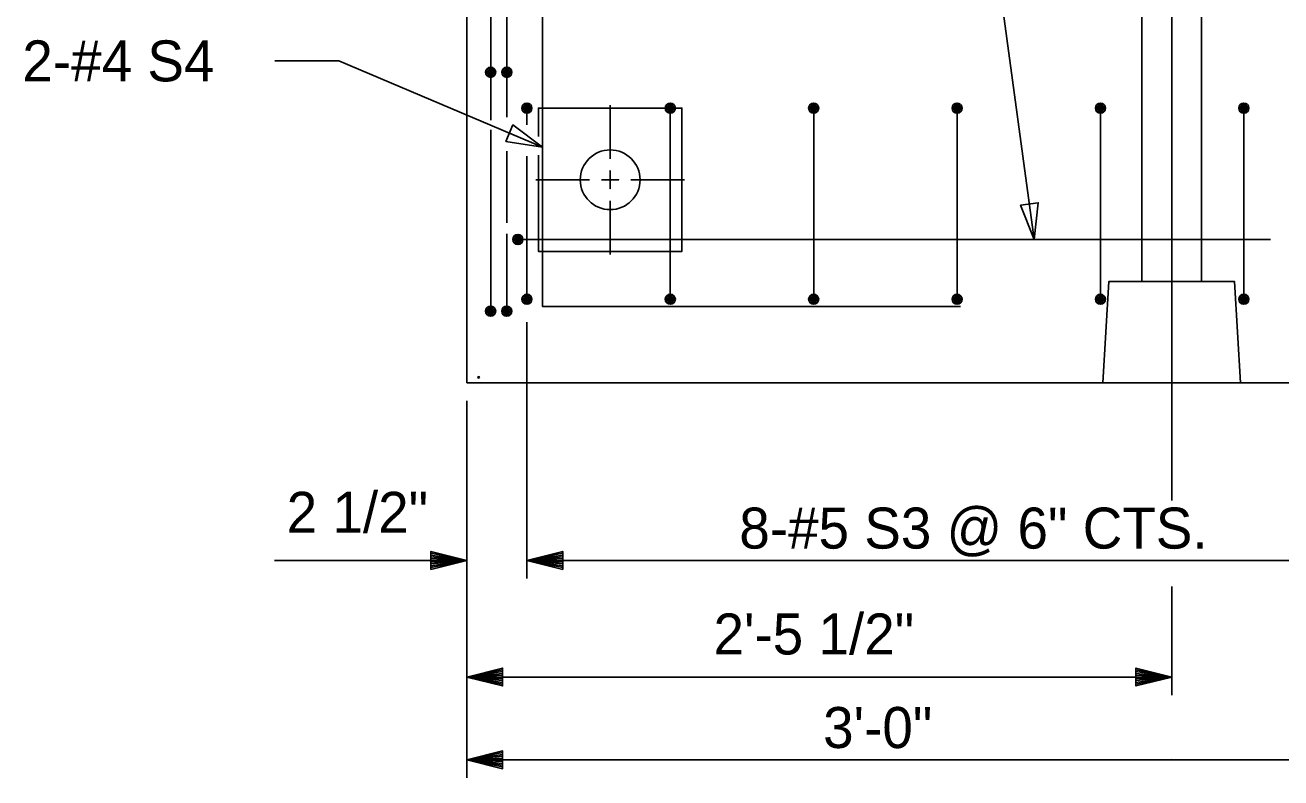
# Model space of a CAD drawing. Extents: x 0 to 177, y -1 to 127.
# Drawn here: x 145.724 to 150.104, y 67.64 to 70.265 of the extents above; entities that cross this region are included whole.
import ezdxf

# ---------------------------------------------------------------- set-up
doc = ezdxf.new("R2010")
doc.units = 0
for name, color, linetype in [('Arrowhead Terminators CELL', 7, 'Continuous'), ('Dimension Lines', 7, 'Continuous'), ('Mis Center Lines', 7, 'Continuous'), ('Rebar Lines', 7, 'Continuous'), ('Sup Concrete Girder Lines', 7, 'Continuous'), ('Sup Cored Slab Unit', 7, 'Continuous'), ('Text', 7, 'Continuous'), ('User Information Notes', 7, 'Continuous')]:
    doc.layers.add(name, color=color, linetype=linetype)

msp = doc.modelspace()

# ---------------------------------------------------------------- linework, layer by layer
at = {"layer": 'Arrowhead Terminators CELL'}
for points in [[(147.528, 69.8396), (147.4251, 69.9172), (147.4007, 69.8596)], [(149.2435, 69.5174), (149.2577, 69.6454), (149.1958, 69.637)]]:
    msp.add_lwpolyline(points, close=True, dxfattribs=at)
at = {"layer": 'Dimension Lines'}
for p, q in [((149.0244, 71.1323), (149.2435, 69.5174)), ((147.7645, 69.7987), (147.7645, 69.9862)), ((147.6929, 69.7257), (147.5054, 69.7257)), ((148.0236, 69.7257), (147.8361, 69.7257)), ((147.7645, 69.4652), (147.7645, 69.6527)), ((147.4743, 68.3352), (147.4743, 69.2288)), ((149.7228, 68.6075), (149.7228, 69.1802)), ((147.2645, 67.6395), (147.2645, 68.9549)), ((146.594, 68.3982), (147.2645, 68.3982)), ((147.4743, 68.3982), (150.9743, 68.3982)), ((149.7228, 67.9283), (149.7228, 68.3067)), ((147.2645, 67.9913), (149.7228, 67.9913)), ((147.2645, 67.7026), (150.2645, 67.7026))]:
    msp.add_line(p, q, dxfattribs=at)
for points in [[(146.5949, 70.1404), (146.8182, 70.1404), (147.528, 69.8396)], [(147.7346, 69.7257), (147.7645, 69.7257), (147.7944, 69.7257), (147.7645, 69.7257), (147.7645, 69.757), (147.7645, 69.7257), (147.7645, 69.6943), (147.7645, 69.7257)], [(147.1395, 68.3982), (147.1395, 68.4044), (147.2645, 68.3982), (147.1395, 68.4107), (147.1395, 68.4169), (147.2645, 68.3982), (147.1395, 68.4232), (147.1395, 68.4294), (147.2645, 68.3982), (147.1395, 68.3669), (147.1395, 68.3732), (147.2645, 68.3982), (147.1395, 68.3794), (147.1395, 68.3857), (147.2645, 68.3982), (147.1395, 68.3919), (147.1395, 68.4294), (147.1395, 68.3669), (147.2645, 68.3982), (147.1395, 68.4294)], [(147.5993, 68.3982), (147.5993, 68.3919), (147.4743, 68.3982), (147.5993, 68.3857), (147.5993, 68.3794), (147.4743, 68.3982), (147.5993, 68.3732), (147.5993, 68.3669), (147.4743, 68.3982), (147.5993, 68.4294), (147.5993, 68.4232), (147.4743, 68.3982), (147.5993, 68.4169), (147.5993, 68.4107), (147.4743, 68.3982), (147.5993, 68.4044), (147.5993, 68.3669), (147.5993, 68.4294), (147.4743, 68.3982), (147.5993, 68.3669)], [(147.3895, 67.9913), (147.3895, 67.9851), (147.2645, 67.9913), (147.3895, 67.9788), (147.3895, 67.9726), (147.2645, 67.9913), (147.3895, 67.9663), (147.3895, 67.9601), (147.2645, 67.9913), (147.3895, 68.0226), (147.3895, 68.0163), (147.2645, 67.9913), (147.3895, 68.0101), (147.3895, 68.0038), (147.2645, 67.9913), (147.3895, 67.9976), (147.3895, 67.9601), (147.3895, 68.0226), (147.2645, 67.9913), (147.3895, 67.9601)], [(149.5978, 67.9913), (149.5978, 67.9976), (149.7228, 67.9913), (149.5978, 68.0038), (149.5978, 68.0101), (149.7228, 67.9913), (149.5978, 68.0163), (149.5978, 68.0226), (149.7228, 67.9913), (149.5978, 67.9601), (149.5978, 67.9663), (149.7228, 67.9913), (149.5978, 67.9726), (149.5978, 67.9788), (149.7228, 67.9913), (149.5978, 67.9851), (149.5978, 68.0226), (149.5978, 67.9601), (149.7228, 67.9913), (149.5978, 68.0226)], [(147.3895, 67.7026), (147.3895, 67.6963), (147.2645, 67.7026), (147.3895, 67.6901), (147.3895, 67.6838), (147.2645, 67.7026), (147.3895, 67.6776), (147.3895, 67.6713), (147.2645, 67.7026), (147.3895, 67.7338), (147.3895, 67.7276), (147.2645, 67.7026), (147.3895, 67.7213), (147.3895, 67.7151), (147.2645, 67.7026), (147.3895, 67.7088), (147.3895, 67.6713), (147.3895, 67.7338), (147.2645, 67.7026), (147.3895, 67.6713)]]:
    msp.add_lwpolyline(points, dxfattribs=at)
at = {"layer": 'Mis Center Lines'}
msp.add_line((149.7228, 69.0174), (149.7228, 72.0174), dxfattribs=at)
at = {"layer": 'Rebar Lines'}
for p, q in [((147.4039, 69.9438), (147.4039, 70.5071)), ((147.3478, 69.9334), (147.3478, 70.3942)), ((147.4743, 69.9177), (147.4743, 69.9756)), ((147.9743, 69.309), (147.9743, 69.9756)), ((148.4743, 69.309), (148.4743, 69.9756)), ((148.9743, 69.309), (148.9743, 69.9756)), ((149.4743, 69.309), (149.4743, 69.9756)), ((149.9743, 69.309), (149.9743, 69.9756)), ((147.3478, 69.2674), (147.3478, 69.8997)), ((147.4039, 69.5752), (147.4039, 69.8251)), ((147.4743, 69.309), (147.4743, 69.8085)), ((147.4039, 69.2674), (147.4039, 69.5373)), ((147.4428, 69.5174), (150.0678, 69.5174))]:
    msp.add_line(p, q, dxfattribs=at)
for points in [[(148.9865, 71.7509), (147.528, 71.7509), (147.528, 69.2843), (148.9865, 69.2843)], [(147.3302, 70.1007), (147.3315, 70.1074), (147.3353, 70.1131), (147.341, 70.117), (147.3478, 70.1183), (147.3545, 70.117), (147.3602, 70.1131), (147.364, 70.1075), (147.3654, 70.1007), (147.364, 70.094), (147.3602, 70.0882), (147.3545, 70.0844), (147.3478, 70.083), (147.341, 70.0844), (147.3353, 70.0882), (147.3315, 70.0939), (147.3302, 70.1007), (147.3478, 70.1007), (147.3654, 70.1007), (147.364, 70.1075), (147.3478, 70.1007), (147.3602, 70.1131), (147.3545, 70.117), (147.3478, 70.1007), (147.3478, 70.1183), (147.341, 70.117), (147.3478, 70.1007), (147.3353, 70.1131), (147.3315, 70.1074), (147.3478, 70.1007), (147.3315, 70.0939), (147.3353, 70.0882), (147.3478, 70.1007), (147.341, 70.0844), (147.3478, 70.083), (147.3478, 70.1007), (147.3545, 70.0844), (147.3602, 70.0882), (147.3478, 70.1007), (147.364, 70.094)], [(147.3863, 70.1007), (147.3876, 70.1074), (147.3914, 70.1131), (147.3972, 70.117), (147.4039, 70.1183), (147.4106, 70.117), (147.4164, 70.1131), (147.4202, 70.1075), (147.4215, 70.1007), (147.4202, 70.094), (147.4164, 70.0882), (147.4107, 70.0844), (147.4039, 70.083), (147.3972, 70.0844), (147.3915, 70.0882), (147.3876, 70.0939), (147.3863, 70.1007), (147.4039, 70.1007), (147.4215, 70.1007), (147.4202, 70.1075), (147.4039, 70.1007), (147.4164, 70.1131), (147.4106, 70.117), (147.4039, 70.1007), (147.4039, 70.1183), (147.3972, 70.117), (147.4039, 70.1007), (147.3914, 70.1131), (147.3876, 70.1074), (147.4039, 70.1007), (147.3876, 70.0939), (147.3915, 70.0882), (147.4039, 70.1007), (147.3972, 70.0844), (147.4039, 70.083), (147.4039, 70.1007), (147.4107, 70.0844), (147.4164, 70.0882), (147.4039, 70.1007), (147.4202, 70.094)], [(147.4567, 69.9756), (147.458, 69.9824), (147.4618, 69.9881), (147.4675, 69.9919), (147.4743, 69.9932), (147.481, 69.9919), (147.4867, 69.9881), (147.4905, 69.9824), (147.4919, 69.9756), (147.4905, 69.9689), (147.4867, 69.9632), (147.4811, 69.9593), (147.4743, 69.958), (147.4675, 69.9593), (147.4618, 69.9631), (147.458, 69.9689), (147.4567, 69.9756), (147.4743, 69.9756), (147.4919, 69.9756), (147.4905, 69.9824), (147.4743, 69.9756), (147.4867, 69.9881), (147.481, 69.9919), (147.4743, 69.9756), (147.4743, 69.9932), (147.4675, 69.9919), (147.4743, 69.9756), (147.4618, 69.9881), (147.458, 69.9824), (147.4743, 69.9756), (147.458, 69.9689), (147.4618, 69.9631), (147.4743, 69.9756), (147.4675, 69.9593), (147.4743, 69.958), (147.4743, 69.9756), (147.4811, 69.9593), (147.4867, 69.9632), (147.4743, 69.9756), (147.4905, 69.9689)], [(147.9567, 69.9756), (147.958, 69.9824), (147.9618, 69.9881), (147.9675, 69.9919), (147.9743, 69.9932), (147.981, 69.9919), (147.9867, 69.9881), (147.9905, 69.9824), (147.9919, 69.9756), (147.9905, 69.9689), (147.9867, 69.9632), (147.9811, 69.9593), (147.9743, 69.958), (147.9675, 69.9593), (147.9618, 69.9631), (147.958, 69.9689), (147.9567, 69.9756), (147.9743, 69.9756), (147.9919, 69.9756), (147.9905, 69.9824), (147.9743, 69.9756), (147.9867, 69.9881), (147.981, 69.9919), (147.9743, 69.9756), (147.9743, 69.9932), (147.9675, 69.9919), (147.9743, 69.9756), (147.9618, 69.9881), (147.958, 69.9824), (147.9743, 69.9756), (147.958, 69.9689), (147.9618, 69.9631), (147.9743, 69.9756), (147.9675, 69.9593), (147.9743, 69.958), (147.9743, 69.9756), (147.9811, 69.9593), (147.9867, 69.9632), (147.9743, 69.9756), (147.9905, 69.9689)], [(148.4567, 69.9756), (148.458, 69.9824), (148.4618, 69.9881), (148.4675, 69.9919), (148.4743, 69.9932), (148.481, 69.9919), (148.4867, 69.9881), (148.4905, 69.9824), (148.4919, 69.9756), (148.4905, 69.9689), (148.4867, 69.9632), (148.4811, 69.9593), (148.4743, 69.958), (148.4675, 69.9593), (148.4618, 69.9631), (148.458, 69.9689), (148.4567, 69.9756), (148.4743, 69.9756), (148.4919, 69.9756), (148.4905, 69.9824), (148.4743, 69.9756), (148.4867, 69.9881), (148.481, 69.9919), (148.4743, 69.9756), (148.4743, 69.9932), (148.4675, 69.9919), (148.4743, 69.9756), (148.4618, 69.9881), (148.458, 69.9824), (148.4743, 69.9756), (148.458, 69.9689), (148.4618, 69.9631), (148.4743, 69.9756), (148.4675, 69.9593), (148.4743, 69.958), (148.4743, 69.9756), (148.4811, 69.9593), (148.4867, 69.9632), (148.4743, 69.9756), (148.4905, 69.9689)], [(148.9567, 69.9756), (148.958, 69.9824), (148.9618, 69.9881), (148.9675, 69.9919), (148.9743, 69.9932), (148.981, 69.9919), (148.9867, 69.9881), (148.9905, 69.9824), (148.9919, 69.9756), (148.9905, 69.9689), (148.9867, 69.9632), (148.9811, 69.9593), (148.9743, 69.958), (148.9675, 69.9593), (148.9618, 69.9631), (148.958, 69.9689), (148.9567, 69.9756), (148.9743, 69.9756), (148.9919, 69.9756), (148.9905, 69.9824), (148.9743, 69.9756), (148.9867, 69.9881), (148.981, 69.9919), (148.9743, 69.9756), (148.9743, 69.9932), (148.9675, 69.9919), (148.9743, 69.9756), (148.9618, 69.9881), (148.958, 69.9824), (148.9743, 69.9756), (148.958, 69.9689), (148.9618, 69.9631), (148.9743, 69.9756), (148.9675, 69.9593), (148.9743, 69.958), (148.9743, 69.9756), (148.9811, 69.9593), (148.9867, 69.9632), (148.9743, 69.9756), (148.9905, 69.9689)], [(149.4567, 69.9756), (149.458, 69.9824), (149.4618, 69.9881), (149.4675, 69.9919), (149.4743, 69.9932), (149.481, 69.9919), (149.4867, 69.9881), (149.4905, 69.9824), (149.4919, 69.9756), (149.4905, 69.9689), (149.4867, 69.9632), (149.4811, 69.9593), (149.4743, 69.958), (149.4675, 69.9593), (149.4618, 69.9631), (149.458, 69.9689), (149.4567, 69.9756), (149.4743, 69.9756), (149.4919, 69.9756), (149.4905, 69.9824), (149.4743, 69.9756), (149.4867, 69.9881), (149.481, 69.9919), (149.4743, 69.9756), (149.4743, 69.9932), (149.4675, 69.9919), (149.4743, 69.9756), (149.4618, 69.9881), (149.458, 69.9824), (149.4743, 69.9756), (149.458, 69.9689), (149.4618, 69.9631), (149.4743, 69.9756), (149.4675, 69.9593), (149.4743, 69.958), (149.4743, 69.9756), (149.4811, 69.9593), (149.4867, 69.9632), (149.4743, 69.9756), (149.4905, 69.9689)], [(149.9567, 69.9756), (149.958, 69.9824), (149.9618, 69.9881), (149.9675, 69.9919), (149.9743, 69.9932), (149.981, 69.9919), (149.9867, 69.9881), (149.9905, 69.9824), (149.9919, 69.9756), (149.9905, 69.9689), (149.9867, 69.9632), (149.9811, 69.9593), (149.9743, 69.958), (149.9675, 69.9593), (149.9618, 69.9631), (149.958, 69.9689), (149.9567, 69.9756), (149.9743, 69.9756), (149.9919, 69.9756), (149.9905, 69.9824), (149.9743, 69.9756), (149.9867, 69.9881), (149.981, 69.9919), (149.9743, 69.9756), (149.9743, 69.9932), (149.9675, 69.9919), (149.9743, 69.9756), (149.9618, 69.9881), (149.958, 69.9824), (149.9743, 69.9756), (149.958, 69.9689), (149.9618, 69.9631), (149.9743, 69.9756), (149.9675, 69.9593), (149.9743, 69.958), (149.9743, 69.9756), (149.9811, 69.9593), (149.9867, 69.9632), (149.9743, 69.9756), (149.9905, 69.9689)], [(147.4252, 69.5174), (147.4265, 69.5241), (147.4303, 69.5298), (147.436, 69.5337), (147.4428, 69.535), (147.4495, 69.5337), (147.4553, 69.5298), (147.4591, 69.5241), (147.4604, 69.5174), (147.4591, 69.5106), (147.4553, 69.5049), (147.4496, 69.5011), (147.4428, 69.4997), (147.436, 69.5011), (147.4304, 69.5049), (147.4265, 69.5106), (147.4252, 69.5174), (147.4428, 69.5174), (147.4604, 69.5174), (147.4591, 69.5241), (147.4428, 69.5174), (147.4553, 69.5298), (147.4495, 69.5337), (147.4428, 69.5174), (147.4428, 69.535), (147.436, 69.5337), (147.4428, 69.5174), (147.4303, 69.5298), (147.4265, 69.5241), (147.4428, 69.5174), (147.4265, 69.5106), (147.4304, 69.5049), (147.4428, 69.5174), (147.436, 69.5011), (147.4428, 69.4997), (147.4428, 69.5174), (147.4496, 69.5011), (147.4553, 69.5049), (147.4428, 69.5174), (147.4591, 69.5106)], [(147.3302, 69.2674), (147.3315, 69.2741), (147.3353, 69.2798), (147.341, 69.2837), (147.3478, 69.285), (147.3545, 69.2837), (147.3602, 69.2798), (147.364, 69.2741), (147.3654, 69.2674), (147.364, 69.2606), (147.3602, 69.2549), (147.3545, 69.2511), (147.3478, 69.2497), (147.341, 69.2511), (147.3353, 69.2549), (147.3315, 69.2606), (147.3302, 69.2674), (147.3478, 69.2674), (147.3654, 69.2674), (147.364, 69.2741), (147.3478, 69.2674), (147.3602, 69.2798), (147.3545, 69.2837), (147.3478, 69.2674), (147.3478, 69.285), (147.341, 69.2837), (147.3478, 69.2674), (147.3353, 69.2798), (147.3315, 69.2741), (147.3478, 69.2674), (147.3315, 69.2606), (147.3353, 69.2549), (147.3478, 69.2674), (147.341, 69.2511), (147.3478, 69.2497), (147.3478, 69.2674), (147.3545, 69.2511), (147.3602, 69.2549), (147.3478, 69.2674), (147.364, 69.2606)], [(147.3862, 69.2674), (147.3875, 69.2741), (147.3913, 69.2798), (147.397, 69.2837), (147.4038, 69.285), (147.4105, 69.2837), (147.4163, 69.2798), (147.4201, 69.2741), (147.4214, 69.2674), (147.4201, 69.2606), (147.4163, 69.2549), (147.4106, 69.2511), (147.4038, 69.2497), (147.397, 69.2511), (147.3914, 69.2549), (147.3875, 69.2606), (147.3862, 69.2674), (147.4038, 69.2674), (147.4214, 69.2674), (147.4201, 69.2741), (147.4038, 69.2674), (147.4163, 69.2798), (147.4105, 69.2837), (147.4038, 69.2674), (147.4038, 69.285), (147.397, 69.2837), (147.4038, 69.2674), (147.3913, 69.2798), (147.3875, 69.2741), (147.4038, 69.2674), (147.3875, 69.2606), (147.3914, 69.2549), (147.4038, 69.2674), (147.397, 69.2511), (147.4038, 69.2497), (147.4038, 69.2674), (147.4106, 69.2511), (147.4163, 69.2549), (147.4038, 69.2674), (147.4201, 69.2606)], [(147.4567, 69.309), (147.458, 69.3157), (147.4618, 69.3214), (147.4675, 69.3253), (147.4743, 69.3266), (147.481, 69.3253), (147.4867, 69.3214), (147.4905, 69.3157), (147.4919, 69.309), (147.4905, 69.3022), (147.4867, 69.2965), (147.4811, 69.2927), (147.4743, 69.2913), (147.4675, 69.2927), (147.4618, 69.2965), (147.458, 69.3022), (147.4567, 69.309), (147.4743, 69.309), (147.4919, 69.309), (147.4905, 69.3157), (147.4743, 69.309), (147.4867, 69.3214), (147.481, 69.3253), (147.4743, 69.309), (147.4743, 69.3266), (147.4675, 69.3253), (147.4743, 69.309), (147.4618, 69.3214), (147.458, 69.3157), (147.4743, 69.309), (147.458, 69.3022), (147.4618, 69.2965), (147.4743, 69.309), (147.4675, 69.2927), (147.4743, 69.2913), (147.4743, 69.309), (147.4811, 69.2927), (147.4867, 69.2965), (147.4743, 69.309), (147.4905, 69.3022)], [(147.9567, 69.309), (147.958, 69.3157), (147.9618, 69.3214), (147.9675, 69.3253), (147.9743, 69.3266), (147.981, 69.3253), (147.9867, 69.3214), (147.9905, 69.3157), (147.9919, 69.309), (147.9905, 69.3022), (147.9867, 69.2965), (147.9811, 69.2927), (147.9743, 69.2913), (147.9675, 69.2927), (147.9618, 69.2965), (147.958, 69.3022), (147.9567, 69.309), (147.9743, 69.309), (147.9919, 69.309), (147.9905, 69.3157), (147.9743, 69.309), (147.9867, 69.3214), (147.981, 69.3253), (147.9743, 69.309), (147.9743, 69.3266), (147.9675, 69.3253), (147.9743, 69.309), (147.9618, 69.3214), (147.958, 69.3157), (147.9743, 69.309), (147.958, 69.3022), (147.9618, 69.2965), (147.9743, 69.309), (147.9675, 69.2927), (147.9743, 69.2913), (147.9743, 69.309), (147.9811, 69.2927), (147.9867, 69.2965), (147.9743, 69.309), (147.9905, 69.3022)], [(148.4567, 69.309), (148.458, 69.3157), (148.4618, 69.3214), (148.4675, 69.3253), (148.4743, 69.3266), (148.481, 69.3253), (148.4867, 69.3214), (148.4905, 69.3157), (148.4919, 69.309), (148.4905, 69.3022), (148.4867, 69.2965), (148.4811, 69.2927), (148.4743, 69.2913), (148.4675, 69.2927), (148.4618, 69.2965), (148.458, 69.3022), (148.4567, 69.309), (148.4743, 69.309), (148.4919, 69.309), (148.4905, 69.3157), (148.4743, 69.309), (148.4867, 69.3214), (148.481, 69.3253), (148.4743, 69.309), (148.4743, 69.3266), (148.4675, 69.3253), (148.4743, 69.309), (148.4618, 69.3214), (148.458, 69.3157), (148.4743, 69.309), (148.458, 69.3022), (148.4618, 69.2965), (148.4743, 69.309), (148.4675, 69.2927), (148.4743, 69.2913), (148.4743, 69.309), (148.4811, 69.2927), (148.4867, 69.2965), (148.4743, 69.309), (148.4905, 69.3022)], [(148.9567, 69.309), (148.958, 69.3157), (148.9618, 69.3214), (148.9675, 69.3253), (148.9743, 69.3266), (148.981, 69.3253), (148.9867, 69.3214), (148.9905, 69.3157), (148.9919, 69.309), (148.9905, 69.3022), (148.9867, 69.2965), (148.9811, 69.2927), (148.9743, 69.2913), (148.9675, 69.2927), (148.9618, 69.2965), (148.958, 69.3022), (148.9567, 69.309), (148.9743, 69.309), (148.9919, 69.309), (148.9905, 69.3157), (148.9743, 69.309), (148.9867, 69.3214), (148.981, 69.3253), (148.9743, 69.309), (148.9743, 69.3266), (148.9675, 69.3253), (148.9743, 69.309), (148.9618, 69.3214), (148.958, 69.3157), (148.9743, 69.309), (148.958, 69.3022), (148.9618, 69.2965), (148.9743, 69.309), (148.9675, 69.2927), (148.9743, 69.2913), (148.9743, 69.309), (148.9811, 69.2927), (148.9867, 69.2965), (148.9743, 69.309), (148.9905, 69.3022)], [(149.4567, 69.309), (149.458, 69.3157), (149.4618, 69.3214), (149.4675, 69.3253), (149.4743, 69.3266), (149.481, 69.3253), (149.4867, 69.3214), (149.4905, 69.3157), (149.4919, 69.309), (149.4905, 69.3022), (149.4867, 69.2965), (149.4811, 69.2927), (149.4743, 69.2913), (149.4675, 69.2927), (149.4618, 69.2965), (149.458, 69.3022), (149.4567, 69.309), (149.4743, 69.309), (149.4919, 69.309), (149.4905, 69.3157), (149.4743, 69.309), (149.4867, 69.3214), (149.481, 69.3253), (149.4743, 69.309), (149.4743, 69.3266), (149.4675, 69.3253), (149.4743, 69.309), (149.4618, 69.3214), (149.458, 69.3157), (149.4743, 69.309), (149.458, 69.3022), (149.4618, 69.2965), (149.4743, 69.309), (149.4675, 69.2927), (149.4743, 69.2913), (149.4743, 69.309), (149.4811, 69.2927), (149.4867, 69.2965), (149.4743, 69.309), (149.4905, 69.3022)], [(149.9567, 69.309), (149.958, 69.3157), (149.9618, 69.3214), (149.9675, 69.3253), (149.9743, 69.3266), (149.981, 69.3253), (149.9867, 69.3214), (149.9905, 69.3157), (149.9919, 69.309), (149.9905, 69.3022), (149.9867, 69.2965), (149.9811, 69.2927), (149.9743, 69.2913), (149.9675, 69.2927), (149.9618, 69.2965), (149.958, 69.3022), (149.9567, 69.309), (149.9743, 69.309), (149.9919, 69.309), (149.9905, 69.3157), (149.9743, 69.309), (149.9867, 69.3214), (149.981, 69.3253), (149.9743, 69.309), (149.9743, 69.3266), (149.9675, 69.3253), (149.9743, 69.309), (149.9618, 69.3214), (149.958, 69.3157), (149.9743, 69.309), (149.958, 69.3022), (149.9618, 69.2965), (149.9743, 69.309), (149.9675, 69.2927), (149.9743, 69.2913), (149.9743, 69.309), (149.9811, 69.2927), (149.9867, 69.2965), (149.9743, 69.309), (149.9905, 69.3022)]]:
    msp.add_lwpolyline(points, dxfattribs=at)
at = {"layer": 'Sup Concrete Girder Lines'}
for p, q in [((147.2645, 69.0174), (147.2645, 72.0174)), ((149.6187, 69.3715), (149.6187, 72.0174)), ((149.827, 69.3715), (149.827, 72.0174)), ((147.2645, 69.0174), (151.8834, 69.0174))]:
    msp.add_line(p, q, dxfattribs=at)
msp.add_lwpolyline([(149.4832, 69.0174), (149.5041, 69.3715), (149.9416, 69.3715), (149.9624, 69.0174)], dxfattribs=at)
for centre, radius in [((147.7645, 69.7257), 0.1042), ((147.306, 69.0366), 0.00273)]:
    msp.add_circle(centre, radius, dxfattribs=at)
at = {"layer": 'Sup Cored Slab Unit'}
msp.add_lwpolyline([(147.5145, 69.8772), (147.5145, 69.9757), (148.0145, 69.9757), (148.0145, 69.4757), (147.5145, 69.4757), (147.5145, 69.8118)], dxfattribs=at)
at = {"layer": 'User Information Notes'}
for p, q in [((147.4039, 69.2674), (147.4039, 69.2674)), ((149.7209, 67.7063), (149.7209, 67.7063))]:
    msp.add_line(p, q, dxfattribs=at)

# ---------------------------------------------------------------- texts
at = {"layer": 'Text'}
for s, height, p in [('2-#4 S4', 0.14302, (145.7146, 70.0689)), ('2 1/2"', 0.14302, (146.6364, 68.4943)), ('8-#5 S3 @ 6" CTS.', 0.143021, (148.2148, 68.4393)), ('2\'-5 1/2"', 0.14302, (148.1249, 68.07)), ('3\'-0"', 0.14302, (148.5072, 67.7437))]:
    msp.add_text(s, height=height, dxfattribs=at).set_placement(p)

doc.saveas('drawing.dxf')
